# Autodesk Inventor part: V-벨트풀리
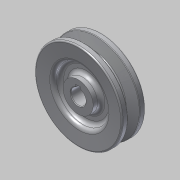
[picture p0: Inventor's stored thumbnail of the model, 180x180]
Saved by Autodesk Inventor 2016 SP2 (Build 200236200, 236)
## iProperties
Created: 2016-08
Part Number: V-벨트풀리
Material: 알루미늄 6061
Document SubType Name: Modeling
Designer: mduedu
Density: 2.71 g/cm^3
Appearance: 알루미늄 - 평지
Author: mduedu
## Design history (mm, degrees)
sketch "스케치1"
  geometry: L1 (0, 9.5)-(0, -9.5); L2 (0, 9.5)-(35, 9.5); L3 (35, 9.5)-(35, 4.825); L4 (35, 4.825)-(26, 2.074); L5 (26, 2.074)-(26, 0); L6 (0, 0)-(26, 0); L7 (0, -9.5)-(35, -9.5); L8 (35, -9.5)-(35, -4.825); L9 (35, -4.825)-(26, -2.074); L10 (26, -2.074)-(26, 0); L11 (32.3, 9.5)-(32.3, -9.5); 3 further points
  constraints: 22 end point, 6 point on line, 4 perpendicular, 3 symmetric about line, 1 coincident, 1 horizontal alignment, 1 midpoint, 1 parallel, 1 vertical
  dimensions: "d0" = 19 distance of L1.start L1.end; "d2" = 70 diameter of L8 L1; "d4" = 6.3 distance between parallel lines of L10 L11; "d5" = 2.7 distance between parallel lines of L11 L8; "d6" = 8 distance of point (32.3, -4) point (32.3, 4); "d7" = 34 deg angle of L9 L4
revolve "회전1" sketch "스케치1" stored, may be unused: angle "d8" = 90 deg
sketch "스케치2"
  geometry: L1 (-2, 0)-(2, 0); L2 (2, 0)-(2, 7.8); L3 (2, 7.8)-(-2, 7.8); L4 (-2, 7.8)-(-2, 0); C1 r 6 at (0, 0); 2 further points
  constraints: 8 end point, 2 coincident, 2 parallel, 1 centre point, 1 horizontal, 1 midpoint, 1 perpendicular
  dimensions: "d9" = 12 diameter of C1; "d11" = 4 distance of L2.end L3.end; "d12" = 7.8 distance of L1.end L2.end
extrude "돌출1" cut sketch "스케치2" stored distance "d13" = 10; taper "d14" = 0 deg
sketch "스케치3"
  geometry: L1 (35, 4.825)-(26, 2.074) reference; L2 (26, 2.074)-(26, -2.074) reference; L3 (0, 0)-(26, 0); L4 (35, 9.5)-(35, 4.825) reference; L5 (-35, 9.5)-(35, 9.5) reference; L6 (35, 9.5)-(21, 8.275); L7 (21, 8.275)-(21, 3); L8 (21, 3)-(12, 3); L9 (12, 3)-(12, 9.5); L10 (0, 9.5)-(0, -9.5); L11 (5.657, -9.5)-(-6, -9.5) reference; L12 (12, 9.5)-(35, 9.5)
  constraints: 14 end point, 3 midpoint, 2 perpendicular, 2 point on line, 1 collinear, 1 horizontal, 1 parallel
  dimensions: "d15" = 3 distance between parallel lines of L3 L8; "d17" = 42 diameter of L7 L10; "d18" = 24 diameter of L9 L10; "d31" = 5 deg angle of L6 L5
revolve "회전2" sketch "스케치3" stored, may be unused: angle "d19" = 90 deg
fillet "모깎기1" dims "d20" = 0.5, "d21" = 1, "d22" = 1
fillet "모깎기2" dims "d23" = 3
fillet "모깎기3" dims "d24" = 3
fillet "모깎기4" dims "d25" = 3
chamfer "모따기1" distance "d26" = 0.5; stored, may be unused: second distance "d27" = 2, angle "d28" = 45 deg
node "솔리드1"
mirror "대칭1"
